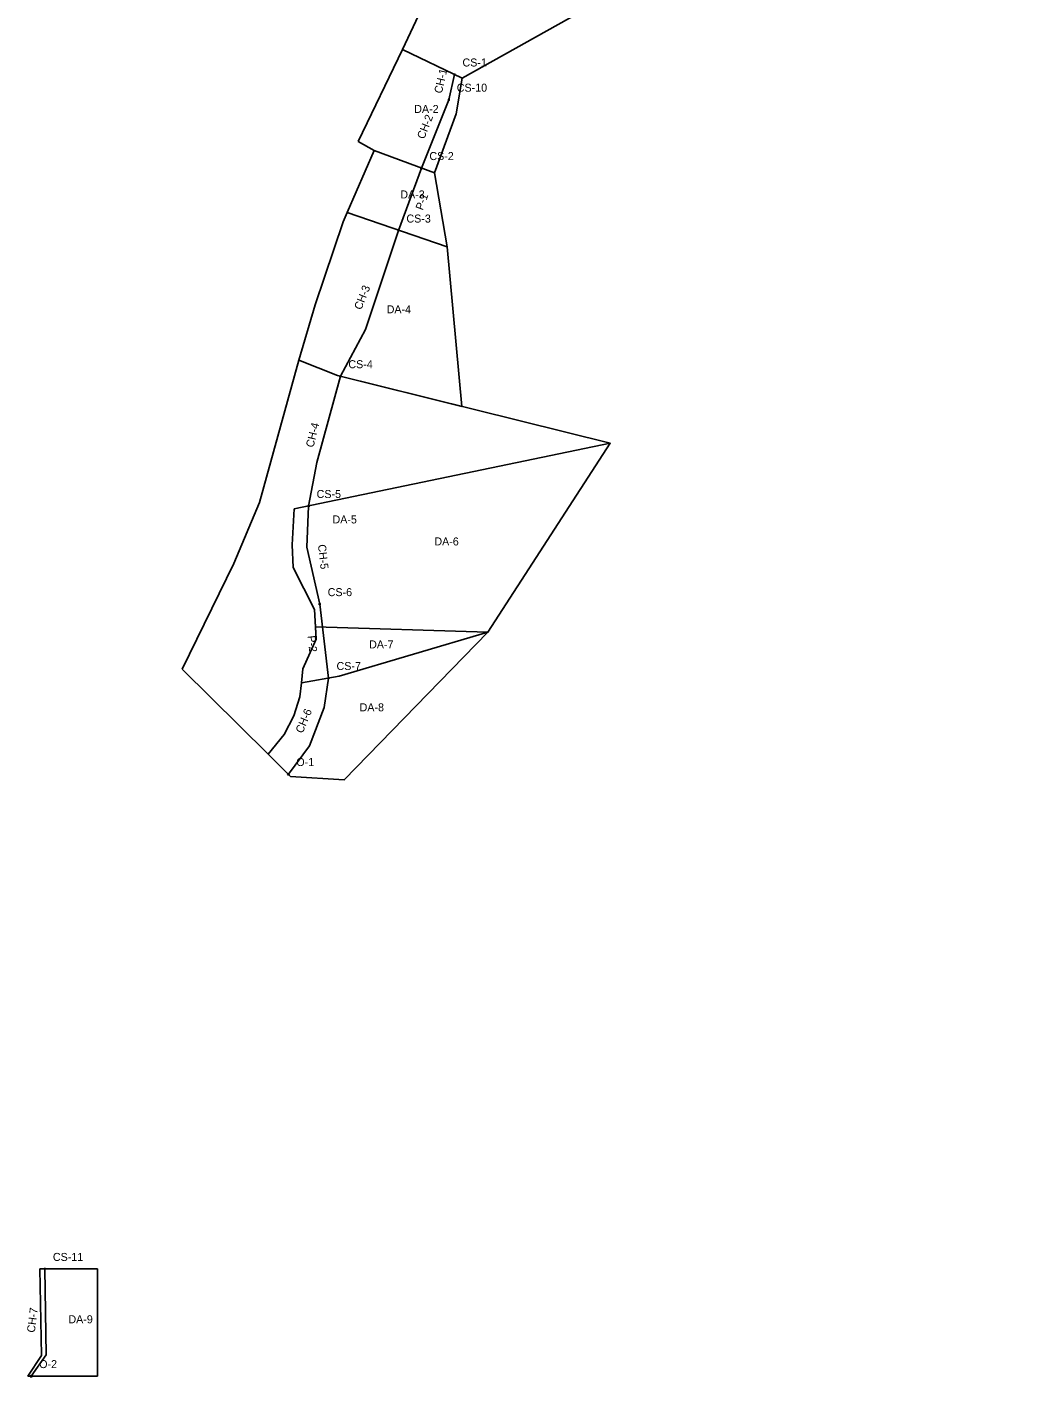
# Model space of a CAD drawing. Extents: x 1564726 to 1565428, y 635990 to 637561.
import ezdxf

# ---------------------------------------------------------------- set-up
doc = ezdxf.new("R2010")
doc.units = 0
for name, color, linetype in [('Default', 7, 'Continuous'), ('DR_P_Cells', 7, 'Continuous'), ('DR_X_Floodway', 7, 'Continuous'), ('DT_X_Break_Line', 7, 'Continuous'), ('DT_X_Contour_Minor', 7, 'Continuous'), ('DT_X_Void', 7, 'Continuous')]:
    doc.layers.add(name, color=color, linetype=linetype)

# ---------------------------------------------------------------- blocks, each defined once
blk = doc.blocks.new('crosssection')
at = {"layer": 'Default'}
for p, q in [((-0.762, 0), (0.762, 0)), ((0, 0.762), (0, -0.762))]:
    blk.add_line(p, q, dxfattribs=at)
blk.add_circle((0, 0), 0.254, dxfattribs=at)
blk = doc.blocks.new('outfall')
at = {"layer": 'Default'}
for p, q in [((-0.635, -0.635), (0, 0.635)), ((0, 0.635), (0.635, -0.635)), ((0.635, -0.635), (-0.635, -0.635))]:
    blk.add_line(p, q, dxfattribs=at)

msp = doc.modelspace()

# ---------------------------------------------------------------- linework, layer by layer
at = {"layer": 'DR_X_Floodway'}
for points in [[(1565002.36, 636835.83), (1564986.31, 636792.1)], [(1564931.23, 636530.68), (1564937.41, 636478.99)]]:
    msp.add_lwpolyline(points, dxfattribs=at)
at = {"layer": 'DT_X_Break_Line'}
for points in [[(1565025.51, 636901.31), (1565021.52, 636883.67)], [(1565021.52, 636883.67), (1565002.36, 636835.83)], [(1564986.31, 636792.1), (1564963.24, 636722.76), (1564945.7, 636690.17)], [(1564945.7, 636690.17), (1564929.33, 636629.77), (1564923.48, 636599.35)], [(1564923.48, 636599.35), (1564922.29, 636570.66), (1564931.23, 636530.68)], [(1564937.41, 636478.99), (1564934.46, 636458.32), (1564924.07, 636431.45), (1564909.29, 636411.79)], [(1564738.98, 636065.49), (1564739.87, 636005.35), (1564729.4, 635990.51)]]:
    msp.add_lwpolyline(points, dxfattribs=at)
at = {"layer": 'DT_X_Void'}
for points in [[(1564989.21, 636918.83), (1565084.74, 637122.17), (1565174.41, 637285.53), (1565303.94, 637561.33), (1565428.13, 637384.13), (1565333.69, 637276.7), (1565310.97, 637178.94), (1565264.96, 637051.05), (1565119.83, 636948.47), (1565030.89, 636898.72)], [(1564958.22, 636854.47), (1564989.21, 636918.83), (1565030.89, 636898.72), (1565026.71, 636873.67), (1565011.61, 636832.39), (1564969.39, 636848.08)], [(1564969.39, 636848.08), (1564950.48, 636804.72), (1565020.37, 636780.62), (1565011.61, 636832.39)], [(1564950.48, 636804.72), (1564947.64, 636798.23), (1564928.1, 636740.14), (1564916.58, 636701.31), (1564943.68, 636690.67), (1565030.63, 636669.05), (1565020.37, 636780.62)], [(1564834.99, 636485.1), (1564871.13, 636559.13), (1564889.03, 636601.7), (1564916.58, 636701.31), (1564943.68, 636690.67), (1565134.5, 636643.22), (1564913.48, 636597.27), (1564911.93, 636572.27), (1564912.76, 636556.39), (1564927.58, 636527.03), (1564928.86, 636506.06), (1564919.42, 636485.35), (1564918.4, 636475.6), (1564917.39, 636465.84), (1564913.19, 636452.58), (1564906.43, 636439.42), (1564895.19, 636425.76)], [(1564913.48, 636597.27), (1565134.5, 636643.22), (1565048.81, 636511.18), (1564928.32, 636514.91), (1564927.58, 636527.03), (1564912.76, 636556.39), (1564911.93, 636572.27)], [(1564895.19, 636425.76), (1564906.43, 636439.42), (1564913.19, 636452.58), (1564917.39, 636465.84), (1564918.4, 636475.6), (1564944.83, 636480.32), (1565048.81, 636511.18), (1564948.43, 636407.72), (1564910.91, 636410.19)], [(1564918.4, 636475.6), (1564919.42, 636485.35), (1564928.86, 636506.06), (1564928.32, 636514.91), (1565048.81, 636511.18), (1564944.83, 636480.32)], [(1564735.44, 636065.49), (1564775.68, 636065.52), (1564775.74, 635990.53), (1564727.12, 635990.5), (1564736.69, 636004.88)]]:
    msp.add_lwpolyline(points, close=True, dxfattribs=at)

# ---------------------------------------------------------------- block references
at = {"layer": 'DT_X_Contour_Minor'}
for name, p in [('crosssection', (1565025.51, 636901.31)), ('crosssection', (1565021.52, 636883.67)), ('crosssection', (1565002.36, 636835.83)), ('crosssection', (1564986.31, 636792.1)), ('crosssection', (1564945.7, 636690.17)), ('crosssection', (1564923.48, 636599.35)), ('crosssection', (1564931.23, 636530.68)), ('crosssection', (1564937.41, 636478.99)), ('outfall', (1564909.29, 636411.79)), ('crosssection', (1564738.98, 636065.49)), ('outfall', (1564729.4, 635990.51))]:
    msp.add_blockref(name, p, dxfattribs=at)

# ---------------------------------------------------------------- texts
at = {"layer": 'DR_P_Cells'}
for s, p in [('CS-1', (1565031.11, 636906.91)), ('CS-10', (1565027.12, 636889.27)), ('DA-2', (1564997.35, 636874.4)), ('CS-2', (1565007.96, 636841.43)), ('DA-3', (1564987.62, 636814.56)), ('CS-3', (1564991.91, 636797.7)), ('DA-4', (1564978.09, 636734.19)), ('CS-4', (1564951.3, 636695.77)), ('CS-5', (1564929.08, 636604.95)), ('DA-5', (1564940.18, 636587.16)), ('DA-6', (1565011.45, 636571.76)), ('CS-6', (1564936.83, 636536.28)), ('DA-7', (1564965.79, 636499.7)), ('CS-7', (1564943.01, 636484.59)), ('DA-8', (1564959.15, 636455.68)), ('O-1', (1564914.89, 636417.39)), ('CS-11', (1564744.58, 636071.09)), ('DA-9', (1564755.44, 636027.47)), ('O-2', (1564735, 635996.11))]:
    msp.add_text(s, height=5.6, dxfattribs=at).set_placement(p)
for s, rotation, p in [('CH-1', 77.22798, (1565016.68, 636887.68)), ('CH-2', 68.18534, (1565004.27, 636855.65)), ('P-1', 69.84114, (1565003.31, 636805.92)), ('CH-3', 68.27735, (1564960.29, 636736.18)), ('CH-4', 76.24812, (1564926.85, 636639.94)), ('CH-5', 276.43942, (1564929.96, 636572.22)), ('P-2', 276.82701, (1564922.62, 636508.38)), ('CH-6', 67.28878, (1564919.24, 636439.89)), ('CH-7', 82.72088, (1564731.9, 636020.67))]:
    msp.add_text(s, height=5.6, rotation=rotation, dxfattribs=at).set_placement(p)

doc.saveas('drawing.dxf')
